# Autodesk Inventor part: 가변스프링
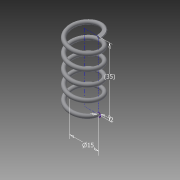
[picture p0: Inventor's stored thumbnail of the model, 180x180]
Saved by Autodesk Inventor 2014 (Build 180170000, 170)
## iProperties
Created: 2017-02
Part Number: 가변스프링
Material: 일반
Document SubType Name: Modeling
Designer: owner
Density: 1 g/cm^3
Appearance: 기본값
Mass: 0.731314 g
Surface Area: 14.8562 cm^2
Volume: 0.731314 cm^3
Author: owner
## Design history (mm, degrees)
sketch "스케치1"
  geometry: L1 (0, 0)-(7.5, 0); L2 (7.5, 0)-(7.5, 35); L3 (7.5, 35)-(0, 35); L4 (0, 35)-(0, 0); C1 r 1 at (7.5, 0)
  constraints: 8 end point, 2 parallel, 1 centre point, 1 coincident, 1 horizontal, 1 perpendicular
  dimensions: "d0" = 15 diameter of L2 L4; "d1" = 35 distance of L1.end L2.end (derived); "d2" = 2 diameter of C1
feature "코일1" pitch "d3" = 10; turns "d5" = 5; dims "d4" = 35 (= d1), "d6" = 0, angle "d7" = 90 deg, angle "d8" = 90 deg, "d9" = 0, "d10" = 0
sketch "스케치2"
  geometry: L1 (-6.5, 0)-(-8.5, 0) reference; 1 further point
  constraints: 1 horizontal alignment
extrude "돌출1" cut sketch "스케치2" stored distance "d11" = 10; taper "d12" = 0 deg
node "작업 평면1"
sketch "스케치3"
  geometry: L1 (-1, 0)-(1, 0) reference; 1 further point
  constraints: 1 horizontal alignment
extrude "돌출2" cut sketch "스케치3" stored distance "d13" = 10; taper "d14" = 0 deg
node "솔리드1"
node "절단 모서리 투영1"
node "절단 모서리 투영2"
